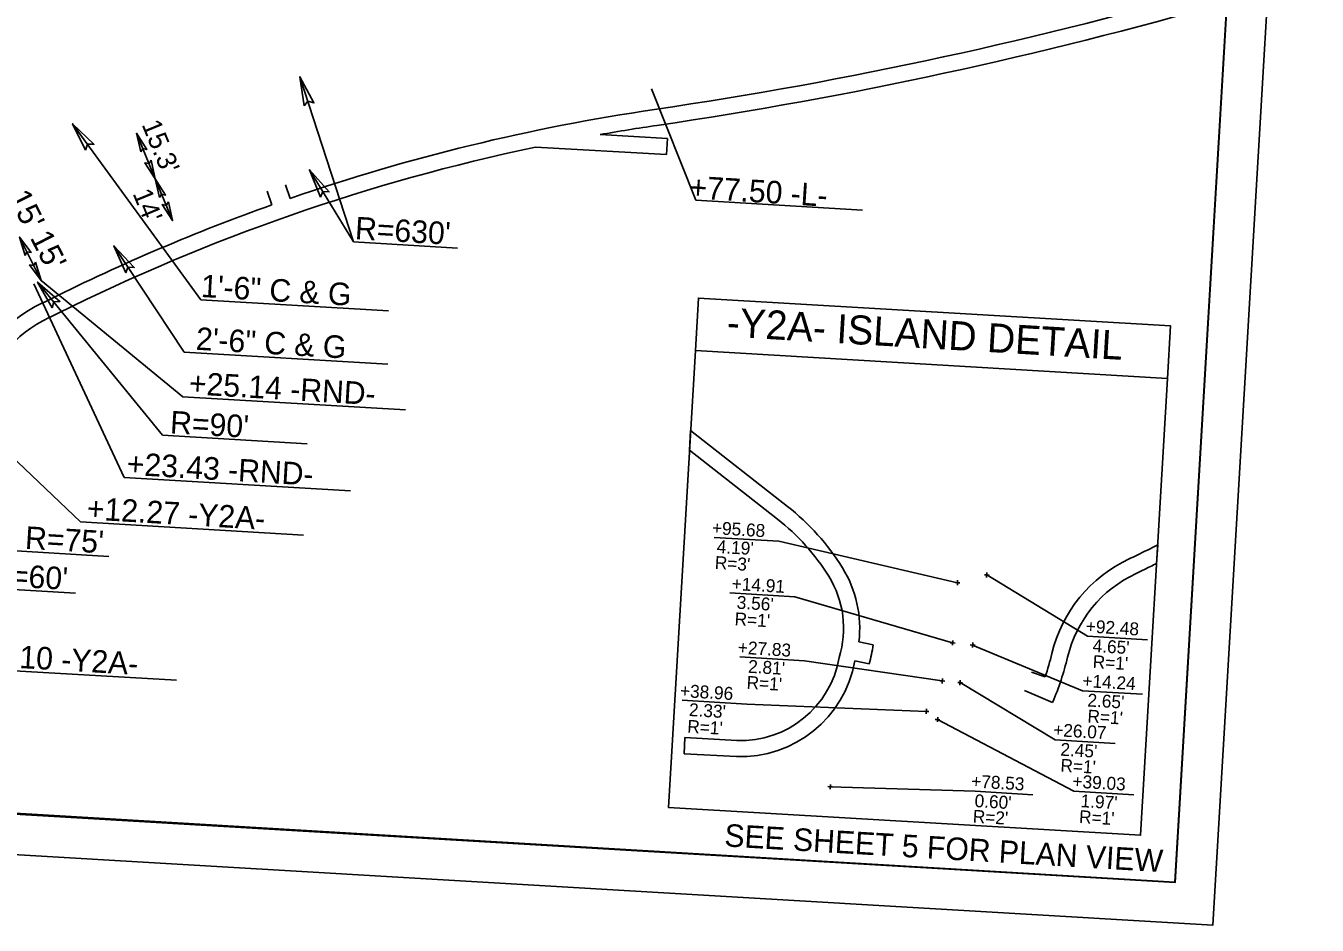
# Model space of a CAD drawing. Extents: x 2012744 to 2013625, y 444638 to 445237.
# Drawn here: x 2013223.7 to 2013624.5, y 444637.7 to 444916.9 of the extents above; entities that cross this region are included whole.
import ezdxf

# ---------------------------------------------------------------- set-up
doc = ezdxf.new("R2010")
doc.units = 0
for name, color, linetype in [('Old_Level_1', 7, 'Continuous'), ('Old_Level_10', 7, 'Continuous'), ('Prop Conc 4in Sidewalk', 7, 'Continuous'), ('Prop Dimension', 7, 'Continuous'), ('Prop Dimension Text', 7, 'Continuous'), ('Prop Shade Medium', 7, 'Continuous'), ('Prop Terminator CELL', 7, 'Continuous'), ('Sheet Clip Boundary CELL', 7, 'Continuous'), ('Sheet Plan And Profile CELL', 7, 'Continuous'), ('Sheet Plot Border Outside CELL', 7, 'Continuous')]:
    doc.layers.add(name, color=color, linetype=linetype)

msp = doc.modelspace()

# ---------------------------------------------------------------- linework, layer by layer
at = {"layer": 'Old_Level_1'}
for points in [[(2013431.51, 444816.05), (2013578.07, 444807.41), (2013579.04, 444823.73), (2013432.47, 444832.37)], [(2013431.51, 444816.05), (2013578.07, 444807.41), (2013569.72, 444665.63), (2013423.15, 444674.27)]]:
    msp.add_lwpolyline(points, close=True, dxfattribs=at)
at = {"layer": 'Prop Conc 4in Sidewalk'}
for p, q in [((2013540.09, 444714.81), (2013535.82, 444716.25)), ((2013542.39, 444706.87), (2013533.66, 444710.61))]:
    msp.add_line(p, q, dxfattribs=at)
for centre, radius, start, end in [((2013414.75, 444709.84), 73.5, 31.8625, 51.9343), ((2013414.75, 444709.84), 68.5, 31.8625, 51.9343), ((2013584.48, 444711.94), 43.5, 114.8702, 166.5654), ((2013525.6, 444838.95), 96.5, 294.8702, 296.4971), ((2013447.02, 444729.9), 35.5, 353.0961, 31.8625), ((2013525.6, 444838.95), 101.5, 294.8702, 296.4971), ((2013584.48, 444711.94), 38.5, 114.8702, 166.5654), ((2013462.9, 444740.98), 81.5, 341.2688, 346.5651), ((2013462.9, 444740.98), 86.5, 336.7743, 346.5651)]:
    msp.add_arc(centre, radius, start, end, dxfattribs=at)
at = {"layer": 'Prop Dimension'}
for p, q in [((2013325.44, 444849.81), (2013308.79, 444901.05)), ((2013417.93, 444897.34), (2013431.7, 444862.72)), ((2013238.2, 444886.48), (2013277.99, 444831.82)), ((2013258.04, 444883.51), (2013263.89, 444869.35)), ((2013325.44, 444849.81), (2013311.73, 444872.18)), ((2013263.89, 444869.35), (2013269.23, 444856.41)), ((2013221.74, 444851.27), (2013228.43, 444837.85)), ((2013251.01, 444848.55), (2013272.85, 444815.62)), ((2013357.72, 444847.9), (2013325.44, 444849.81)), ((2013226.13, 444836.74), (2013254.25, 444776.66)), ((2013266.13, 444789.77), (2013227.34, 444837.31)), ((2013228.43, 444837.85), (2013272.38, 444801.72)), ((2013277.99, 444831.82), (2013336.25, 444828.38)), ((2013336.02, 444811.9), (2013272.85, 444815.62)), ((2013198.53, 444803), (2013240.71, 444762.87)), ((2013341.57, 444797.64), (2013272.38, 444801.72)), ((2013311.06, 444787.12), (2013266.13, 444789.77)), ((2013324.5, 444772.51), (2013254.25, 444776.66)), ((2013309.9, 444758.79), (2013240.71, 444762.87)), ((2013457.45, 444756.9), (2013437.36, 444758.08)), ((2013512.87, 444744.03), (2013457.45, 444756.9)), ((2013249.43, 444752.17), (2013215.37, 444754.18)), ((2013521.97, 444746.43), (2013553.25, 444727.4)), ((2013239.15, 444740.76), (2013204.22, 444742.82)), ((2013462.34, 444739.67), (2013442.25, 444740.85)), ((2013462.34, 444739.67), (2013511.36, 444725.34)), ((2013571.87, 444726.31), (2013553.25, 444727.4)), ((2013517.57, 444724.68), (2013551.63, 444710.51)), ((2013465.39, 444719.81), (2013445.3, 444720.99)), ((2013465.39, 444719.81), (2013508.16, 444713.53)), ((2013270.49, 444713.73), (2013201.3, 444717.81)), ((2013513.68, 444713), (2013543.24, 444695.24)), ((2013447.51, 444706.36), (2013427.42, 444707.54)), ((2013570.25, 444709.41), (2013551.63, 444710.51)), ((2013447.51, 444706.36), (2013503.23, 444704.09)), ((2013506.68, 444701.54), (2013549.03, 444679.28)), ((2013561.86, 444694.14), (2013543.24, 444695.24)), ((2013473.37, 444680.68), (2013518.34, 444679.27)), ((2013536.31, 444678.21), (2013518.34, 444679.27)), ((2013567.65, 444678.18), (2013549.03, 444679.28))]:
    msp.add_line(p, q, dxfattribs=at)
at = {"layer": 'Prop Dimension Text'}
for p, q in [((2013431.7, 444862.72), (2013483.35, 444859.68)), ((2013522.01, 444747.17), (2013521.92, 444745.68)), ((2013512.87, 444744.03), (2013512.12, 444744.08)), ((2013512.91, 444744.78), (2013512.83, 444743.29)), ((2013512.87, 444744.03), (2013513.62, 444743.99)), ((2013521.97, 444746.43), (2013521.22, 444746.47)), ((2013521.97, 444746.43), (2013522.72, 444746.38)), ((2013511.36, 444725.34), (2013510.61, 444725.39)), ((2013511.4, 444726.09), (2013511.31, 444724.59)), ((2013511.36, 444725.34), (2013512.11, 444725.3)), ((2013517.57, 444724.68), (2013516.82, 444724.72)), ((2013517.61, 444725.42), (2013517.52, 444723.93)), ((2013517.57, 444724.68), (2013518.31, 444724.63)), ((2013508.16, 444713.53), (2013507.41, 444713.58)), ((2013508.2, 444714.28), (2013508.11, 444712.78)), ((2013508.16, 444713.53), (2013508.91, 444713.49)), ((2013513.68, 444713), (2013512.93, 444713.05)), ((2013513.72, 444713.75), (2013513.63, 444712.25)), ((2013513.68, 444713), (2013514.42, 444712.96)), ((2013503.23, 444704.09), (2013502.48, 444704.14)), ((2013503.27, 444704.84), (2013503.19, 444703.34)), ((2013503.23, 444704.09), (2013503.98, 444704.05)), ((2013506.68, 444701.54), (2013505.93, 444701.59)), ((2013506.73, 444702.29), (2013506.64, 444700.79)), ((2013506.68, 444701.54), (2013507.43, 444701.5)), ((2013473.37, 444680.68), (2013472.63, 444680.72)), ((2013473.42, 444681.42), (2013473.33, 444679.93)), ((2013473.37, 444680.68), (2013474.12, 444680.63))]:
    msp.add_line(p, q, dxfattribs=at)
at = {"layer": 'Prop Shade Medium'}
for p, q in [((2013381.89, 444879.22), (2013422.54, 444876.93)), ((2013422.83, 444881.92), (2013401.92, 444883.1)), ((2013422.54, 444876.93), (2013422.83, 444881.92)), ((2013305.72, 444863.28), (2013304.25, 444867.52)), ((2013298.59, 444865.55), (2013300.1, 444861.31)), ((2013429.69, 444785.15), (2013430.05, 444791.22)), ((2013430.05, 444791.22), (2013460.06, 444767.71)), ((2013456.98, 444763.77), (2013429.69, 444785.15)), ((2013574.69, 444750), (2013575.03, 444755.72)), ((2013482.26, 444725.64), (2013486.68, 444724.72)), ((2013485.46, 444718.84), (2013481.02, 444719.76)), ((2013540.09, 444714.81), (2013535.82, 444716.25)), ((2013533.66, 444710.61), (2013542.39, 444706.87)), ((2013428, 444690.93), (2013428.27, 444695.93)), ((2013428.27, 444695.93), (2013444.43, 444695.06)), ((2013444.24, 444690.06), (2013428, 444690.93))]:
    msp.add_line(p, q, dxfattribs=at)
for centre, radius, start, end in [((2013223.9, 446217.91), 1341.25, 278.35841, 286.14038), ((2013223.9, 446217.91), 1346.25, 278.35841, 286.06498), ((2013509.51, 444274.03), 623.5, 98.35841, 109.07758), ((2013509.51, 444274.03), 618.5, 98.35841, 100.0179), ((2013509.51, 444274.03), 618.5, 101.90818, 116.49713), ((2013509.51, 444274.03), 623.5, 109.62496, 116.49713), ((2013188.28, 444918.4), 96.5, 294.8702, 296.4971), ((2013247.16, 444791.38), 43.5, 114.8702, 166.5654), ((2013188.28, 444918.4), 101.5, 294.8702, 296.4971), ((2013247.16, 444791.38), 38.5, 114.8702, 166.5654), ((2013414.75, 444709.84), 73.5, 31.8625, 51.9343), ((2013414.75, 444709.84), 68.5, 31.8625, 51.9343), ((2013846.83, 444194.59), 623.5, 115.84471, 116.49713), ((2013584.48, 444711.94), 43.5, 114.8702, 166.5654), ((2013525.6, 444838.95), 96.5, 294.8702, 296.4971), ((2013447.02, 444729.9), 35.5, 353.0961, 31.8625), ((2013846.83, 444194.59), 618.5, 116.1041, 116.49713), ((2013447.02, 444729.9), 30.5, 342.6037, 31.8625), ((2013584.48, 444711.94), 38.5, 114.8702, 166.5654), ((2013447.02, 444729.9), 40, 343.9472, 352.5576), ((2013445.59, 444726.01), 35.98, 267.8497, 349.9973), ((2013445.59, 444726.01), 30.98, 267.8497, 350.2796), ((2013462.9, 444740.98), 81.5, 341.2688, 346.5651), ((2013462.9, 444740.98), 86.5, 336.7743, 346.5651)]:
    msp.add_arc(centre, radius, start, end, dxfattribs=at)
at = {"layer": 'Prop Terminator CELL'}
for points in [[(2013310.1, 444892.01), (2013308.79, 444901.05), (2013313.11, 444892.93), (2013311.23, 444893.53)], [(2013242.24, 444878.29), (2013238.2, 444886.48), (2013244.82, 444880.1), (2013242.85, 444880.09)], [(2013259.34, 444877.72), (2013258.04, 444883.51), (2013261.25, 444878.47), (2013260, 444878.77)], [(2013262.59, 444875.14), (2013263.89, 444869.35), (2013260.68, 444874.39), (2013261.93, 444874.09)], [(2013315.11, 444863.69), (2013311.73, 444872.18), (2013317.82, 444865.3), (2013315.86, 444865.44)], [(2013265.19, 444863.56), (2013263.89, 444869.35), (2013267.09, 444864.31), (2013265.85, 444864.6)], [(2013267.93, 444862.2), (2013269.23, 444856.41), (2013266.02, 444861.45), (2013267.27, 444861.15)], [(2013223.45, 444845.59), (2013221.74, 444851.27), (2013225.3, 444846.47), (2013224.03, 444846.68)], [(2013254.69, 444840.19), (2013251.01, 444848.55), (2013257.34, 444841.89), (2013255.38, 444841.97)], [(2013226.72, 444843.53), (2013228.43, 444837.85), (2013224.88, 444842.65), (2013226.14, 444842.45)], [(2013231.83, 444829.36), (2013227.34, 444837.31), (2013234.3, 444831.31), (2013232.34, 444831.19)]]:
    msp.add_lwpolyline(points, close=True, dxfattribs=at)
at = {"layer": 'Sheet Clip Boundary CELL'}
for points in [[(2013605.95, 445084.18), (2013506.09, 445090.07), (2013509.49, 445147.63), (2013409.64, 445153.51), (2013411.6, 445186.8), (2012862.6, 445219.16), (2012831.71, 444695.07), (2013580.41, 444650.94)], [(2012832.37, 444695.56), (2012863.22, 445218.85), (2013411.41, 445186.54), (2013409.45, 445153.34), (2013509.31, 445147.45), (2013505.92, 445089.85), (2013605.86, 445083.96), (2013580.34, 444651.05)]]:
    msp.add_lwpolyline(points, close=True, dxfattribs=at)
at = {"layer": 'Sheet Plan And Profile CELL'}
msp.add_lwpolyline([(2013611.3, 445175.03), (2012862.6, 445219.16), (2012831.71, 444695.07), (2013580.41, 444650.94)], close=True, dxfattribs=at)
at = {"layer": 'Sheet Plot Border Outside CELL'}
msp.add_lwpolyline([(2012743.62, 444687.74), (2013592.15, 444637.73), (2013624.51, 445186.77), (2012775.99, 445236.79)], close=True, dxfattribs=at)

# ---------------------------------------------------------------- texts
at = {"layer": 'Old_Level_10'}
for s, p in [('+95.68', (2013436.58, 444759.11)), ("4.19'", (2013438.06, 444753.28)), ("R=3'", (2013437.46, 444748.32)), ('+14.91', (2013442.73, 444741.8)), ("3.56'", (2013444.27, 444735.97)), ("R=1'", (2013443.61, 444730.84)), ('+92.48', (2013552.62, 444728.59)), ('+27.83', (2013444.61, 444722.01)), ("4.65'", (2013554.74, 444722.52)), ("2.81'", (2013447.8, 444716.08)), ("R=1'", (2013554.75, 444717.55)), ("R=1'", (2013447.33, 444711.12)), ('+14.24', (2013551.58, 444711.66)), ('+38.96', (2013426.66, 444708.57)), ("2.65'", (2013553.12, 444705.62)), ("2.33'", (2013429.44, 444702.66)), ("R=1'", (2013553.13, 444700.65)), ("R=1'", (2013428.92, 444697.48)), ('+26.07', (2013542.51, 444696.43)), ("2.45'", (2013544.73, 444690.35)), ("R=1'", (2013544.74, 444685.38)), ('+78.53', (2013517.05, 444680.5)), ('+39.03', (2013548.48, 444680.46)), ("0.60'", (2013518.1, 444674.4)), ("1.97'", (2013551, 444674.37)), ("R=2'", (2013517.53, 444669.55)), ("R=1'", (2013550.52, 444669.43))]:
    msp.add_text(s, height=4, rotation=356.6264, dxfattribs=at).set_placement(p)
at = {"layer": 'Prop Dimension'}
for s, height, p in [('-Y2A- ISLAND DETAIL', 9, (2013441.1, 444820.42)), ('SEE SHEET 5 FOR PLAN VIEW', 7, (2013440.38, 444662.19))]:
    msp.add_text(s, height=height, rotation=356.6264, dxfattribs=at).set_placement(p)
at = {"layer": 'Prop Dimension Text'}
for s, height, rotation, p in [("15.3'", 6, 292.4204, (2013259.56, 444886.27)), ('+77.50 -L-', 7, 356.3956, (2013429.5, 444863.4)), ("15'", 7, 297.0252, (2013218.06, 444863.79)), ("14'", 6, 292.4204, (2013256.77, 444864.83)), ("R=630'", 7, 356.6264, (2013325.73, 444850.64)), ("15'", 7, 297.0252, (2013224.87, 444851.14)), ('1\'-6" C & G', 7, 356.6264, (2013277.91, 444832.71)), ('2\'-6" C & G', 7, 356.6264, (2013276.33, 444816.34)), ('+25.14 -RND-', 7, 356.6264, (2013274.16, 444802.54)), ("R=90'", 7, 356.6264, (2013268.33, 444790.4)), ('+23.43 -RND-', 7, 356.6264, (2013254.89, 444777.55)), ('+12.27 -Y2A-', 7, 356.6264, (2013242.49, 444763.69)), ("R=75'", 7, 356.6264, (2013223.31, 444754.56)), ("R=60'", 7, 356.6264, (2013212.16, 444743.2)), ('+47.10 -Y2A-', 7, 356.6264, (2013203.08, 444718.63))]:
    msp.add_text(s, height=height, rotation=rotation, dxfattribs=at).set_placement(p)

doc.saveas('drawing.dxf')
